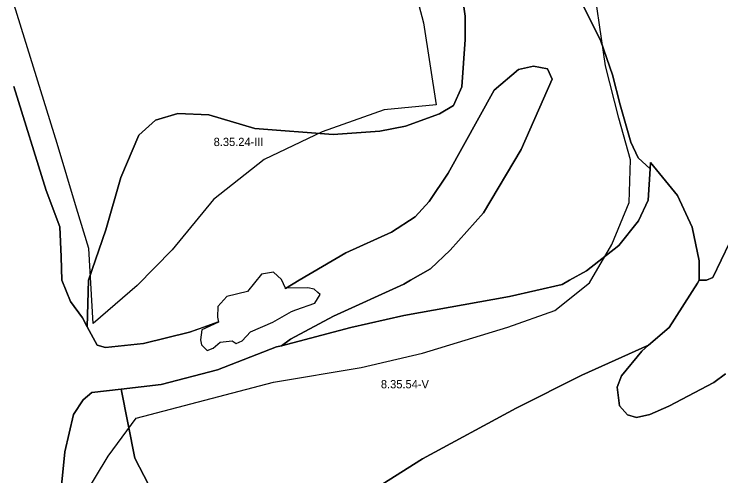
# Model space of a CAD drawing. Extents: x -547623 to -533936, y -1096714 to -1086523.
# Drawn here: x -540837 to -539983, y -1093236 to -1092678 of the extents above; entities that cross this region are included whole.
import ezdxf

# ---------------------------------------------------------------- set-up
doc = ezdxf.new("R2010")
doc.units = 0
for name, color, linetype in [('Vrstva 27', 7, 'Continuous'), ('Vrstva 28', 7, 'Continuous'), ('Vrstva 29', 7, 'Continuous')]:
    doc.layers.add(name, color=color, linetype=linetype)

msp = doc.modelspace()

# ---------------------------------------------------------------- linework, layer by layer
at = {"layer": 'Vrstva 28'}
for p, q in [((-540163.5, -1092639.5), (-540128, -1092711)), ((-540128, -1092711), (-540163.5, -1092639.5)), ((-540292, -1092681), (-540296.5, -1092649.5)), ((-540296.5, -1092649.5), (-540292, -1092681)), ((-540292, -1092709), (-540292, -1092681)), ((-540292, -1092681), (-540292, -1092709)), ((-540296, -1092766.5), (-540292, -1092709)), ((-540292, -1092709), (-540296, -1092766.5)), ((-540128, -1092711), (-540114, -1092752)), ((-540114, -1092752), (-540128, -1092711)), ((-540209.5, -1092741.5), (-540227.5, -1092745.5)), ((-540192.5, -1092744.5), (-540209.5, -1092741.5)), ((-540227.5, -1092745.5), (-540257, -1092770.5)), ((-540187, -1092757), (-540192.5, -1092744.5)), ((-540224.5, -1092842), (-540187, -1092757)), ((-540114, -1092752), (-540105, -1092788)), ((-540105, -1092788), (-540114, -1092752)), ((-540798, -1092891.5), (-540837, -1092766)), ((-540306, -1092789), (-540296, -1092766.5)), ((-540296, -1092766.5), (-540306, -1092789)), ((-540257, -1092770.5), (-540312.5, -1092870.5)), ((-540323, -1092799), (-540306, -1092789)), ((-540306, -1092789), (-540323, -1092799)), ((-540105, -1092788), (-540092, -1092833)), ((-540092, -1092833), (-540105, -1092788)), ((-540666, -1092806.5), (-540639, -1092798.5)), ((-540639, -1092798.5), (-540666, -1092806.5)), ((-540639, -1092798.5), (-540601.5, -1092800)), ((-540601.5, -1092800), (-540639, -1092798.5)), ((-540601.5, -1092800), (-540546, -1092816.5)), ((-540546, -1092816.5), (-540601.5, -1092800)), ((-540364, -1092814), (-540323, -1092799)), ((-540323, -1092799), (-540364, -1092814)), ((-540686, -1092824.5), (-540666, -1092806.5)), ((-540666, -1092806.5), (-540686, -1092824.5)), ((-540546, -1092816.5), (-540451.5, -1092824)), ((-540451.5, -1092824), (-540546, -1092816.5)), ((-540395, -1092820), (-540364, -1092814)), ((-540364, -1092814), (-540395, -1092820)), ((-540708, -1092876), (-540686, -1092824.5)), ((-540686, -1092824.5), (-540708, -1092876)), ((-540451.5, -1092824), (-540395, -1092820)), ((-540395, -1092820), (-540451.5, -1092824)), ((-540092, -1092833), (-540083, -1092852)), ((-540083, -1092852), (-540092, -1092833)), ((-540270, -1092918.5), (-540224.5, -1092842)), ((-540083, -1092852), (-540068.5, -1092865.5)), ((-540068.5, -1092865.5), (-540083, -1092852)), ((-540068.5, -1092865.5), (-540068, -1092857.5)), ((-540068, -1092857.5), (-540068.5, -1092865.5)), ((-540068, -1092857.5), (-540035.5, -1092897.5)), ((-540035.5, -1092897.5), (-540068, -1092857.5)), ((-540312.5, -1092870.5), (-540335.5, -1092905)), ((-540068.5, -1092865.5), (-540071, -1092903)), ((-540071, -1092903), (-540068.5, -1092865.5)), ((-540726, -1092939), (-540708, -1092876)), ((-540708, -1092876), (-540726, -1092939)), ((-540781.5, -1092935.5), (-540798, -1092891.5)), ((-540335.5, -1092905), (-540352.5, -1092923.5)), ((-540071, -1092903), (-540082.5, -1092928)), ((-540082.5, -1092928), (-540071, -1092903)), ((-540035.5, -1092897.5), (-540018, -1092936)), ((-540018, -1092936), (-540035.5, -1092897.5)), ((-540310, -1092963.5), (-540270, -1092918.5)), ((-539954, -1092915.5), (-539993, -1092996.5)), ((-539993, -1092996.5), (-539954, -1092915.5)), ((-540352.5, -1092923.5), (-540381, -1092942)), ((-540082.5, -1092928), (-540106.5, -1092958)), ((-540106.5, -1092958), (-540082.5, -1092928)), ((-540780, -1092971.5), (-540781.5, -1092935.5)), ((-540747, -1093000), (-540726, -1092939)), ((-540726, -1092939), (-540747, -1093000)), ((-540018, -1092936), (-540009.5, -1092976.5)), ((-540009.5, -1092976.5), (-540018, -1092936)), ((-540381, -1092942), (-540436, -1092967)), ((-540334, -1092986), (-540310, -1092963.5)), ((-540106.5, -1092958), (-540145.5, -1092988.5)), ((-540145.5, -1092988.5), (-540106.5, -1092958)), ((-540779, -1093000), (-540780, -1092971.5)), ((-540436, -1092967), (-540492.38, -1093000)), ((-540009.5, -1092976.5), (-540009.5, -1093000)), ((-540009.5, -1093000), (-540009.5, -1092976.5)), ((-540358.22, -1093000), (-540334, -1092986)), ((-540145.5, -1092988.5), (-540166.06, -1093000)), ((-540166.06, -1093000), (-540145.5, -1092988.5)), ((-539993, -1092996.5), (-540000.62, -1093000)), ((-540000.62, -1093000), (-539993, -1092996.5)), ((-540768.5, -1093025.5), (-540779, -1093000)), ((-540748.5, -1093056), (-540747, -1093000)), ((-540747, -1093000), (-540748.5, -1093056)), ((-540492.38, -1093000), (-540509.2, -1093009.85)), ((-540451, -1093043.5), (-540366, -1093004.5)), ((-540366, -1093004.5), (-540358.22, -1093000)), ((-540175, -1093005), (-540238.5, -1093019.5)), ((-540238.5, -1093019.5), (-540175, -1093005)), ((-540166.06, -1093000), (-540175, -1093005)), ((-540175, -1093005), (-540166.06, -1093000)), ((-540011.5, -1093003.5), (-540045.5, -1093057)), ((-540045.5, -1093057), (-540011.5, -1093003.5)), ((-540009.5, -1093000), (-540011.5, -1093003.5)), ((-540011.5, -1093003.5), (-540009.5, -1093000)), ((-540007.28, -1093000), (-540009.5, -1093000)), ((-540009.5, -1093000), (-540007.28, -1093000)), ((-540000.62, -1093000), (-540007.28, -1093000)), ((-540007.28, -1093000), (-540000.62, -1093000)), ((-540238.5, -1093019.5), (-540366, -1093042.5)), ((-540366, -1093042.5), (-540238.5, -1093019.5)), ((-540754, -1093045.5), (-540768.5, -1093025.5)), ((-540748.5, -1093056), (-540754, -1093045.5)), ((-540503, -1093071), (-540451, -1093043.5)), ((-540366, -1093042.5), (-540430, -1093057)), ((-540430, -1093057), (-540366, -1093042.5)), ((-540736.5, -1093078.5), (-540748.5, -1093056)), ((-540589.84, -1093050.47), (-540625, -1093062.5)), ((-540430, -1093057), (-540514, -1093079)), ((-540514, -1093079), (-540430, -1093057)), ((-540045.5, -1093057), (-540070.5, -1093078.5)), ((-540070.5, -1093078.5), (-540045.5, -1093057)), ((-540625, -1093062.5), (-540680.5, -1093076.5)), ((-540514, -1093079), (-540503, -1093071)), ((-540726.5, -1093081), (-540736.5, -1093078.5)), ((-540680.5, -1093076.5), (-540726.5, -1093081)), ((-540591, -1093108), (-540520, -1093080.5)), ((-540520, -1093080.5), (-540514, -1093079)), ((-540070.5, -1093078.5), (-540151, -1093114.5)), ((-540151, -1093114.5), (-540070.5, -1093078.5)), ((-540070.5, -1093078.5), (-540078.5, -1093085.5)), ((-540078.5, -1093085.5), (-540070.5, -1093078.5)), ((-540078.5, -1093085.5), (-540103, -1093115.5)), ((-540103, -1093115.5), (-540078.5, -1093085.5)), ((-540659, -1093126), (-540591, -1093108)), ((-540151, -1093114.5), (-540230.5, -1093154.5)), ((-540230.5, -1093154.5), (-540151, -1093114.5)), ((-540103, -1093115.5), (-540108.5, -1093129)), ((-540108.5, -1093129), (-540103, -1093115.5)), ((-539991.5, -1093123.5), (-539977.5, -1093113)), ((-539977.5, -1093113), (-539991.5, -1093123.5)), ((-540707.5, -1093131.48), (-540659, -1093126)), ((-540046, -1093152), (-539991.5, -1093123.5)), ((-539991.5, -1093123.5), (-540046, -1093152)), ((-540753.5, -1093144.5), (-540743, -1093135.5)), ((-540743, -1093135.5), (-540707.5, -1093131.48)), ((-540707.5, -1093131.48), (-540691, -1093215)), ((-540691, -1093215), (-540707.5, -1093131.48)), ((-540108.5, -1093129), (-540105.5, -1093151.5)), ((-540105.5, -1093151.5), (-540108.5, -1093129)), ((-540765, -1093162), (-540753.5, -1093144.5)), ((-540105.5, -1093151.5), (-540096, -1093162.5)), ((-540096, -1093162.5), (-540105.5, -1093151.5)), ((-540069, -1093162), (-540046, -1093152)), ((-540046, -1093152), (-540069, -1093162)), ((-540230.5, -1093154.5), (-540343.5, -1093215.5)), ((-540343.5, -1093215.5), (-540230.5, -1093154.5)), ((-540775.5, -1093207), (-540765, -1093162)), ((-540096, -1093162.5), (-540085, -1093165.5)), ((-540085, -1093165.5), (-540096, -1093162.5)), ((-540085, -1093165.5), (-540069, -1093162)), ((-540069, -1093162), (-540085, -1093165.5)), ((-540780, -1093252), (-540775.5, -1093207)), ((-540691, -1093215), (-540674.5, -1093246.5)), ((-540674.5, -1093246.5), (-540691, -1093215)), ((-540343.5, -1093215.5), (-540392.5, -1093246.5)), ((-540392.5, -1093246.5), (-540343.5, -1093215.5))]:
    msp.add_line(p, q, dxfattribs=at)
for points in [[(-540509.2, -1093009.85), (-540492.38, -1093000), (-540436, -1092967), (-540381, -1092942), (-540352.5, -1092923.5), (-540335.5, -1092905), (-540312.5, -1092870.5), (-540257, -1092770.5), (-540227.5, -1092745.5), (-540209.5, -1092741.5), (-540192.5, -1092744.5), (-540187, -1092757), (-540224.5, -1092842), (-540270, -1092918.5), (-540310, -1092963.5), (-540334, -1092986), (-540358.22, -1093000), (-540366, -1093004.5), (-540451, -1093043.5), (-540503, -1093071), (-540514, -1093079), (-540430, -1093057), (-540366, -1093042.5), (-540238.5, -1093019.5), (-540175, -1093005), (-540166.06, -1093000), (-540145.5, -1092988.5), (-540106.5, -1092958), (-540082.5, -1092928), (-540071, -1092903), (-540068.5, -1092865.5), (-540083, -1092852), (-540092, -1092833), (-540105, -1092788), (-540114, -1092752), (-540128, -1092711), (-540163.5, -1092639.5)], [(-540163.5, -1092639.5), (-540128, -1092711), (-540114, -1092752), (-540105, -1092788), (-540092, -1092833), (-540083, -1092852), (-540068.5, -1092865.5), (-540068, -1092857.5), (-540035.5, -1092897.5), (-540018, -1092936), (-540009.5, -1092976.5), (-540009.5, -1093000), (-540007.28, -1093000), (-540000.62, -1093000), (-539993, -1092996.5), (-539954, -1092915.5)], [(-540666, -1092806.5), (-540639, -1092798.5), (-540601.5, -1092800), (-540546, -1092816.5), (-540451.5, -1092824), (-540395, -1092820), (-540364, -1092814), (-540323, -1092799), (-540306, -1092789), (-540296, -1092766.5), (-540292, -1092709), (-540292, -1092681), (-540296.5, -1092649.5)], [(-540296.5, -1092649.5), (-540292, -1092681), (-540292, -1092709), (-540296, -1092766.5), (-540306, -1092789), (-540323, -1092799), (-540364, -1092814), (-540395, -1092820), (-540451.5, -1092824), (-540546, -1092816.5)], [(-540509.2, -1093009.85), (-540492.38, -1093000), (-540436, -1092967), (-540381, -1092942), (-540352.5, -1092923.5), (-540335.5, -1092905), (-540312.5, -1092870.5), (-540257, -1092770.5), (-540227.5, -1092745.5), (-540209.5, -1092741.5), (-540192.5, -1092744.5), (-540187, -1092757), (-540224.5, -1092842), (-540270, -1092918.5), (-540310, -1092963.5), (-540334, -1092986), (-540358.22, -1093000), (-540366, -1093004.5), (-540451, -1093043.5), (-540503, -1093071), (-540514, -1093079), (-540520, -1093080.5), (-540591, -1093108), (-540659, -1093126), (-540707.5, -1093131.48), (-540743, -1093135.5), (-540753.5, -1093144.5), (-540765, -1093162), (-540775.5, -1093207), (-540780, -1093252)], [(-540837, -1092766), (-540798, -1092891.5), (-540781.5, -1092935.5), (-540780, -1092971.5), (-540779, -1093000), (-540768.5, -1093025.5), (-540754, -1093045.5), (-540748.5, -1093056), (-540747, -1093000), (-540726, -1092939), (-540708, -1092876), (-540686, -1092824.5), (-540666, -1092806.5)], [(-540837, -1092766), (-540798, -1092891.5), (-540781.5, -1092935.5), (-540780, -1092971.5), (-540779, -1093000), (-540768.5, -1093025.5), (-540754, -1093045.5), (-540748.5, -1093056), (-540736.5, -1093078.5), (-540726.5, -1093081), (-540680.5, -1093076.5), (-540625, -1093062.5), (-540589.99, -1093050.03)], [(-540546, -1092816.5), (-540601.5, -1092800), (-540639, -1092798.5), (-540666, -1092806.5), (-540686, -1092824.5), (-540708, -1092876), (-540726, -1092939), (-540747, -1093000), (-540748.5, -1093056), (-540736.5, -1093078.5), (-540726.5, -1093081), (-540680.5, -1093076.5), (-540625, -1093062.5), (-540590.75, -1093050.3)], [(-540392.5, -1093246.5), (-540343.5, -1093215.5), (-540230.5, -1093154.5), (-540151, -1093114.5), (-540070.5, -1093078.5), (-540045.5, -1093057), (-540011.5, -1093003.5), (-540009.5, -1093000), (-540009.5, -1092976.5), (-540018, -1092936), (-540035.5, -1092897.5), (-540068, -1092857.5), (-540068.5, -1092865.5), (-540071, -1092903), (-540082.5, -1092928), (-540106.5, -1092958), (-540145.5, -1092988.5), (-540166.06, -1093000), (-540175, -1093005), (-540238.5, -1093019.5), (-540366, -1093042.5), (-540430, -1093057), (-540514, -1093079), (-540520, -1093080.5), (-540591, -1093108), (-540659, -1093126), (-540707.5, -1093131.48), (-540691, -1093215), (-540674.5, -1093246.5)], [(-540508.5, -1093009.44), (-540508.98, -1093009.45), (-540513.94, -1092999.08), (-540523.67, -1092990.16), (-540538.12, -1092992.42), (-540554.8, -1093013.37), (-540580.06, -1093019.62), (-540590.77, -1093031.59), (-540591.08, -1093044.38)], [(-540591.08, -1093044.38), (-540589.84, -1093050.47), (-540610.13, -1093059.61), (-540611.67, -1093071.75), (-540610.63, -1093077.8), (-540603.81, -1093084.69), (-540596.31, -1093081.85), (-540587.8, -1093074.59), (-540573.58, -1093073.17), (-540568.76, -1093076.14), (-540561.33, -1093073.24), (-540551.15, -1093062.08), (-540524.2, -1093050.73), (-540501.74, -1093037.49), (-540496.68, -1093035.83), (-540473.74, -1093027.56), (-540467.28, -1093017.1), (-540469.9, -1093014.73)], [(-540509.67, -1093008.95), (-540509.2, -1093009.85)], [(-540469.9, -1093014.73), (-540474.22, -1093010.83), (-540482.17, -1093008.91), (-540508.5, -1093009.44), (-540509.2, -1093009.85), (-540508.5, -1093009.44)]]:
    msp.add_lwpolyline(points, dxfattribs=at)
at = {"layer": 'Vrstva 29'}
for points in [[(-540358.9, -1092626.13), (-540342.23, -1092689.15), (-540327.19, -1092788.1), (-540389.79, -1092794.09), (-540464.85, -1092820.48), (-540534.81, -1092854.09), (-540595.9, -1092902.49), (-540646.03, -1092963.1), (-540688.11, -1093006.15), (-540741.24, -1093052.09), (-540746.47, -1092961.64), (-540761.62, -1092912.86), (-540784.83, -1092834.79), (-540852.7, -1092614.84)], [(-540766.62, -1093284.42), (-540723.19, -1093212.58), (-540689.25, -1093166.6), (-540523.5, -1093123.19), (-540417.63, -1093105.28), (-540343.56, -1093087.99), (-540240.29, -1093056.48), (-540183.56, -1093036.28), (-540141.78, -1093002.93), (-540114.72, -1092956.71), (-540094.08, -1092905.95), (-540092.31, -1092854.67), (-540106.49, -1092803.96), (-540122.65, -1092740.99), (-540139.89, -1092622.33)]]:
    msp.add_lwpolyline(points, dxfattribs=at)

# ---------------------------------------------------------------- texts
at = {"layer": 'Vrstva 27'}
for s, p in [('8.35.24-III', (-540595.77, -1092837.85)), ('8.35.54-V', (-540393.8, -1093130.47))]:
    msp.add_text(s, height=10, dxfattribs=at).set_placement(p)

doc.saveas('drawing.dxf')
